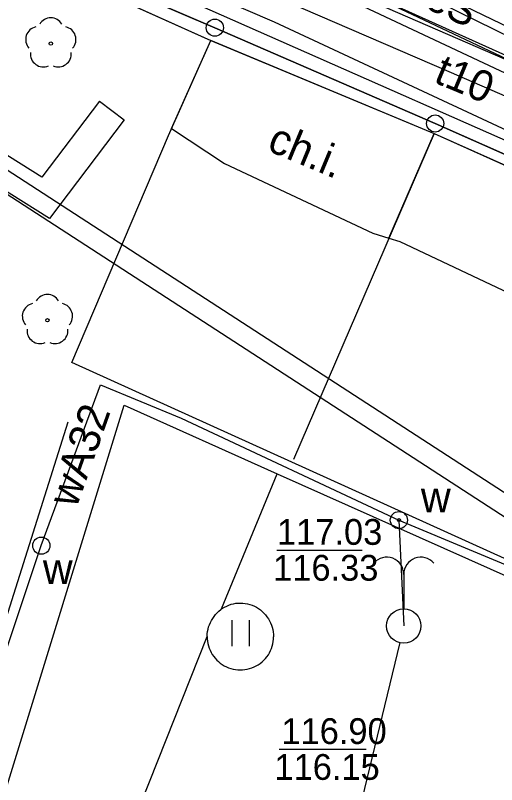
# Model space of a CAD drawing. Extents: x 6434771 to 6436222, y 5663454 to 5664782.
# Drawn here: x 6434897.1 to 6434911.12, y 5664046.13 to 5664068.5 of the extents above; entities that cross this region are included whole.
import ezdxf

# ---------------------------------------------------------------- set-up
doc = ezdxf.new("R2010")
doc.units = 0
for name, color, linetype in [('Warstwa 1', 7, 'Continuous'), ('Warstwa 10', 7, 'Continuous'), ('Warstwa 11', 7, 'Continuous'), ('Warstwa 12', 7, 'Continuous'), ('Warstwa 13', 7, 'Continuous'), ('Warstwa 14', 7, 'Continuous'), ('Warstwa 2', 7, 'Continuous'), ('Warstwa 32', 7, 'Continuous'), ('Warstwa 4', 7, 'Continuous'), ('Warstwa 5', 7, 'Continuous'), ('Warstwa 51', 7, 'Continuous'), ('Warstwa 6', 7, 'Continuous'), ('Warstwa 7', 7, 'Continuous'), ('Warstwa 8', 7, 'Continuous'), ('Warstwa 9', 7, 'Continuous')]:
    doc.layers.add(name, color=color, linetype=linetype)

msp = doc.modelspace()

# ---------------------------------------------------------------- linework, layer by layer
at = {"layer": 'Warstwa 1'}
for p, q in [((6434896.533, 5664070.874), (6434902.911, 5664068.147)), ((6434896.533, 5664070.874), (6434902.911, 5664068.147)), ((6434902.911, 5664068.147), (6434909.328, 5664065.359)), ((6434902.911, 5664068.147), (6434909.328, 5664065.359)), ((6434909.328, 5664065.359), (6434918.181, 5664061.441)), ((6434909.328, 5664065.359), (6434918.181, 5664061.441))]:
    msp.add_line(p, q, dxfattribs=at)
at = {"layer": 'Warstwa 10'}
for points in [[(6435039.27, 5663995.38), (6435030.2, 5664000.49), (6435026.78, 5664002.49), (6435005.3, 5664015.02), (6435001.82, 5664020.36), (6434989.95, 5664026.95), (6434987.82, 5664026.16), (6434986.6, 5664026.34), (6434978.53, 5664030.75), (6434978.42, 5664032.99), (6434977.19, 5664033.85), (6434965.42, 5664040.09), (6434950.99, 5664047.76), (6434936.21, 5664055.56), (6434923.51, 5664061.95), (6434922, 5664062.6), (6434919.82, 5664061.67), (6434916.14, 5664063.34), (6434915.04, 5664064.99), (6434913.7, 5664066.79), (6434899.99, 5664073.52), (6434899.07, 5664073.93), (6434899.76, 5664075.88), (6434904.43, 5664090.76)], [(6434898.671, 5664074.419), (6434902.76, 5664072.365), (6434912.576, 5664067.627), (6434922.039, 5664062.843), (6434928.491, 5664059.745), (6434937.421, 5664055.317), (6434945.409, 5664050.998), (6434960.407, 5664042.783), (6434962.523, 5664038.882), (6434979.882, 5664029.167), (6434995.86, 5664020.139), (6435019.103, 5664006.754), (6435039.449, 5663995.035), (6435046.546, 5663989.977), (6435049.657, 5663987.84), (6435051.881, 5663986.317), (6435053.049, 5663985.633), (6435057.374, 5663981.038), (6435060.712, 5663977.517), (6435062.186, 5663975.788), (6435062.844, 5663975.005)], [(6434897.799, 5664073.869), (6434902.99, 5664071.376), (6434906.697, 5664069.461), (6434912.456, 5664066.861), (6434925.794, 5664060.729), (6434928.609, 5664060.01), (6434931.137, 5664057.624), (6434949.054, 5664048.986), (6434962.469, 5664041.023), (6434978.882, 5664032.044), (6434990.046, 5664026.529), (6434993.502, 5664024.497), (6435013.504, 5664012.944), (6435029.359, 5664004.111), (6435038.639, 5663997.479)], [(6434896.42, 5664071.06), (6434898.16, 5664073.03), (6434900.23, 5664072.06), (6434923.31, 5664061.23), (6434926.55, 5664059.81), (6434927.25, 5664060), (6434930.24, 5664058.57), (6434930.73, 5664057.88), (6434948.57, 5664048.49), (6434986.66, 5664027.63), (6435008.6, 5664015.27), (6435029.24, 5664003.72), (6435037.15, 5663998.25), (6435049.94, 5663990.19), (6435056.65, 5663985.18), (6435065.79, 5663976.31), (6435067.86, 5663972.11), (6435071.01, 5663962.36), (6435072.82, 5663959.6), (6435082.35, 5663954.64), (6435097.639, 5663946.244)]]:
    msp.add_lwpolyline(points, dxfattribs=at)
for centre in [(6434902.911, 5664068.147), (6434902.911, 5664068.147), (6434909.328, 5664065.359), (6434909.328, 5664065.359)]:
    msp.add_circle(centre, 0.25, dxfattribs=at)
at = {"layer": 'Warstwa 11'}
for centre in [(6434898.135, 5664067.685), (6434898.037, 5664059.636)]:
    msp.add_circle(centre, 0.05, dxfattribs=at)
for centre, start, end in [((6434898.135, 5664068.06), 30.1471, 149.8529), ((6434897.778, 5664067.801), 102.1471, 221.8529), ((6434898.492, 5664067.801), 318.1471, 77.8529), ((6434897.915, 5664067.382), 174.1471, 293.8529), ((6434898.355, 5664067.382), 246.1471, 5.8529), ((6434898.037, 5664060.011), 30.1471, 149.8529), ((6434897.68, 5664059.752), 102.1471, 221.8529), ((6434898.394, 5664059.752), 318.1471, 77.8529), ((6434897.817, 5664059.333), 174.1471, 293.8529), ((6434898.257, 5664059.333), 246.1471, 5.8529)]:
    msp.add_arc(centre, 0.375, start, end, dxfattribs=at)
at = {"layer": 'Warstwa 12'}
for points in [[(6434879.175, 5664080.266), (6434887.31, 5664077.322), (6434892.172, 5664075.523), (6434893.714, 5664075.077), (6434894.712, 5664074.689), (6434895.613, 5664074.144), (6434901.244, 5664071.622), (6434919.521, 5664063.703), (6434922.709, 5664066.16)], [(6434879.17, 5664079.837), (6434888.273, 5664076.673), (6434888.682, 5664076.42), (6434889.766, 5664075.059), (6434890.197, 5664074.339), (6434897.825, 5664070.973), (6434901.691, 5664069.15), (6434915.855, 5664062.899), (6434925.788, 5664058.47), (6434925.899, 5664058.551), (6434931.693, 5664069.373), (6434935.652, 5664076.954)], [(6434879.158, 5664078.856), (6434884.466, 5664077.041), (6434884.943, 5664076.892), (6434885.361, 5664076.61), (6434904.643, 5664068.316), (6434925.269, 5664058.705), (6434945.05, 5664048.685), (6434974.567, 5664032.476), (6434974.989, 5664032.261), (6434975.127, 5664032.48), (6434976.891, 5664035.328), (6434977.019, 5664035.547), (6434977.471, 5664035.311), (6435021.423, 5664010.318), (6435021.865, 5664010.097), (6435021.856, 5664009.772), (6435020.661, 5664007.687), (6435020.508, 5664007.434), (6435020.935, 5664007.143), (6435043.134, 5663993.734), (6435056.442, 5663986.832), (6435065.286, 5663979.645), (6435065.567, 5663979.291)], [(6435076.981, 5663977.987), (6435060.8, 5663986.83), (6435044.672, 5663995.689), (6435035.779, 5664000.664), (6435026.559, 5664005.848), (6435021.216, 5664008.862), (6435015.543, 5664011.986), (6435005.727, 5664017.515), (6434993.895, 5664024.292), (6434988.15, 5664027.391), (6434986.652, 5664028.144), (6434985.953, 5664028.56), (6434978.495, 5664032.512), (6434971.253, 5664036.441), (6434966.665, 5664038.927), (6434949.941, 5664048.002), (6434948.145, 5664048.942), (6434947.222, 5664049.507), (6434943.986, 5664051.256), (6434934.8, 5664055.982), (6434925.516, 5664060.59), (6434905.925, 5664069.826), (6434896.606, 5664074.336), (6434894.752, 5664075.227)], [(6434922.621, 5664060.807), (6434921.342, 5664061.827), (6434909.738, 5664066.86), (6434900.244, 5664070.967), (6434893.585, 5664073.988), (6434892.737, 5664074.562)], [(6434885.395, 5664013.843), (6434885.756, 5664014.964), (6434886.868, 5664018.391), (6434887.895, 5664021.449), (6434889.709, 5664026.787), (6434891.413, 5664032.026), (6434892.752, 5664036.89), (6434894.005, 5664041.255), (6434895.856, 5664047.122), (6434897.858, 5664053.078), (6434899.585, 5664057.757), (6434901.933, 5664056.788), (6434908.273, 5664053.821), (6434914.766, 5664051.112), (6434915.042, 5664051.579), (6434915.735, 5664051.851), (6434916.557, 5664052.021), (6434918.057, 5664051.142), (6434918.098, 5664051.124), (6434921.598, 5664049.539), (6434922.532, 5664051.558), (6434923.03, 5664051.342), (6434925.581, 5664050.171)], [(6434908.273, 5664053.821), (6434908.415, 5664050.742)]]:
    msp.add_lwpolyline(points, dxfattribs=at)
at = {"layer": 'Warstwa 14'}
for p, q in [((6434907.207, 5664052.94), (6434904.715, 5664052.94)), ((6434907.321, 5664047.147), (6434904.786, 5664047.147))]:
    msp.add_line(p, q, dxfattribs=at)
msp.add_circle((6434908.273, 5664053.821), 0.045, dxfattribs=at)
at = {"layer": 'Warstwa 2'}
for points in [[(6434878.725, 5664042.975), (6434879.824, 5664045.447), (6434885.357, 5664054.75), (6434896.533, 5664070.874), (6434897.518, 5664070.15), (6434902.796, 5664067.777)], [(6434901.563, 5664065.013), (6434902.796, 5664067.777)], [(6434902.788, 5664067.781), (6434909.299, 5664065.072)], [(6434938.699, 5664047.811), (6434932.805, 5664050.893), (6434931.278, 5664047.842), (6434922.18, 5664052.192), (6434921.428, 5664050.352), (6434915.161, 5664053.198), (6434914.349, 5664051.348), (6434898.743, 5664058.407), (6434901.563, 5664065.013)], [(6434909.299, 5664065.072), (6434905.207, 5664055.585)], [(6434909.299, 5664065.072), (6434918.25, 5664061.052)], [(6434885.156, 5664013.984), (6434898.642, 5664056.678)]]:
    msp.add_lwpolyline(points, dxfattribs=at)
at = {"layer": 'Warstwa 32'}
msp.add_line((6434908.415, 5664052.242), (6434908.415, 5664051.242), dxfattribs=at)
msp.add_circle((6434908.415, 5664050.742), 0.5, dxfattribs=at)
for centre, start, end in [((6434907.915, 5664052.242), 0, 138.5904), ((6434908.915, 5664052.242), 41.4096, 180)]:
    msp.add_arc(centre, 0.5, start, end, dxfattribs=at)
at = {"layer": 'Warstwa 4'}
for centre in [(6434908.273, 5664053.821), (6434897.858, 5664053.078)]:
    msp.add_circle(centre, 0.25, dxfattribs=at)
at = {"layer": 'Warstwa 5'}
for p, q in [((6434903.138, 5664051.256), (6434903.198, 5664051.291)), ((6434903.198, 5664051.291), (6434903.259, 5664051.322)), ((6434903.259, 5664051.322), (6434903.323, 5664051.349)), ((6434903.323, 5664051.349), (6434903.389, 5664051.371)), ((6434903.389, 5664051.371), (6434903.456, 5664051.388)), ((6434903.456, 5664051.388), (6434903.524, 5664051.4)), ((6434903.524, 5664051.4), (6434903.593, 5664051.407)), ((6434903.593, 5664051.407), (6434903.662, 5664051.409)), ((6434903.662, 5664051.409), (6434903.731, 5664051.406)), ((6434903.731, 5664051.406), (6434903.799, 5664051.398)), ((6434903.799, 5664051.398), (6434903.867, 5664051.385)), ((6434903.867, 5664051.385), (6434903.934, 5664051.367)), ((6434903.934, 5664051.367), (6434903.999, 5664051.345)), ((6434903.999, 5664051.345), (6434904.063, 5664051.317)), ((6434904.063, 5664051.317), (6434904.124, 5664051.286)), ((6434904.124, 5664051.286), (6434904.183, 5664051.249)), ((6434902.889, 5664051.02), (6434902.932, 5664051.074)), ((6434902.932, 5664051.074), (6434902.978, 5664051.125)), ((6434902.978, 5664051.125), (6434903.028, 5664051.172)), ((6434903.028, 5664051.172), (6434903.082, 5664051.216)), ((6434903.082, 5664051.216), (6434903.11, 5664051.236)), ((6434903.11, 5664051.236), (6434903.138, 5664051.256)), ((6434904.183, 5664051.249), (6434904.239, 5664051.209)), ((6434904.239, 5664051.209), (6434904.292, 5664051.165)), ((6434904.292, 5664051.165), (6434904.342, 5664051.117)), ((6434904.342, 5664051.117), (6434904.388, 5664051.065)), ((6434904.388, 5664051.065), (6434904.43, 5664051.01)), ((6434902.755, 5664050.778), (6434902.782, 5664050.842)), ((6434902.782, 5664050.842), (6434902.814, 5664050.903)), ((6434902.814, 5664050.903), (6434902.85, 5664050.962)), ((6434902.85, 5664050.962), (6434902.889, 5664051.02)), ((6434903.421, 5664050.156), (6434903.421, 5664050.906)), ((6434903.921, 5664050.156), (6434903.921, 5664050.906)), ((6434904.43, 5664051.01), (6434904.47, 5664050.953)), ((6434904.47, 5664050.953), (6434904.505, 5664050.894)), ((6434904.505, 5664050.894), (6434904.536, 5664050.832)), ((6434904.536, 5664050.832), (6434904.563, 5664050.768)), ((6434902.701, 5664050.577), (6434902.714, 5664050.645)), ((6434902.714, 5664050.645), (6434902.732, 5664050.712)), ((6434902.732, 5664050.712), (6434902.755, 5664050.778)), ((6434904.563, 5664050.768), (6434904.585, 5664050.702)), ((6434904.585, 5664050.702), (6434904.602, 5664050.635)), ((6434904.602, 5664050.635), (6434904.614, 5664050.567)), ((6434902.69, 5664050.439), (6434902.693, 5664050.509)), ((6434902.69, 5664050.439), (6434902.692, 5664050.37)), ((6434902.693, 5664050.509), (6434902.701, 5664050.577)), ((6434904.614, 5664050.567), (6434904.622, 5664050.498)), ((6434904.622, 5664050.498), (6434904.624, 5664050.429)), ((6434904.622, 5664050.36), (6434904.624, 5664050.429)), ((6434902.692, 5664050.37), (6434902.698, 5664050.301)), ((6434902.698, 5664050.301), (6434902.71, 5664050.233)), ((6434902.71, 5664050.233), (6434902.726, 5664050.166)), ((6434902.726, 5664050.166), (6434902.748, 5664050.1)), ((6434904.563, 5664050.09), (6434904.585, 5664050.156)), ((6434904.585, 5664050.156), (6434904.602, 5664050.223)), ((6434904.602, 5664050.223), (6434904.614, 5664050.291)), ((6434904.614, 5664050.291), (6434904.622, 5664050.36)), ((6434902.748, 5664050.1), (6434902.773, 5664050.035)), ((6434902.773, 5664050.035), (6434902.804, 5664049.973)), ((6434902.804, 5664049.973), (6434902.839, 5664049.913)), ((6434904.47, 5664049.904), (6434904.505, 5664049.964)), ((6434904.505, 5664049.964), (6434904.536, 5664050.026)), ((6434904.536, 5664050.026), (6434904.563, 5664050.09)), ((6434902.839, 5664049.913), (6434902.878, 5664049.856)), ((6434902.878, 5664049.856), (6434902.921, 5664049.802)), ((6434902.921, 5664049.802), (6434902.968, 5664049.751)), ((6434902.968, 5664049.751), (6434903.018, 5664049.703)), ((6434903.018, 5664049.703), (6434903.071, 5664049.659)), ((6434904.288, 5664049.696), (6434904.339, 5664049.743)), ((6434904.339, 5664049.743), (6434904.386, 5664049.794)), ((6434904.386, 5664049.794), (6434904.43, 5664049.848)), ((6434904.43, 5664049.848), (6434904.47, 5664049.904)), ((6434903.071, 5664049.659), (6434903.128, 5664049.619)), ((6434903.128, 5664049.619), (6434903.187, 5664049.583)), ((6434903.187, 5664049.583), (6434903.249, 5664049.552)), ((6434903.249, 5664049.552), (6434903.313, 5664049.525)), ((6434903.313, 5664049.525), (6434903.379, 5664049.503)), ((6434903.379, 5664049.503), (6434903.446, 5664049.485)), ((6434903.446, 5664049.485), (6434903.514, 5664049.472)), ((6434903.79, 5664049.471), (6434903.858, 5664049.483)), ((6434903.858, 5664049.483), (6434903.925, 5664049.5)), ((6434903.925, 5664049.5), (6434903.991, 5664049.521)), ((6434903.991, 5664049.521), (6434904.055, 5664049.548)), ((6434904.055, 5664049.548), (6434904.117, 5664049.578)), ((6434904.117, 5664049.578), (6434904.177, 5664049.614)), ((6434904.177, 5664049.614), (6434904.234, 5664049.653)), ((6434904.234, 5664049.653), (6434904.288, 5664049.696)), ((6434903.514, 5664049.472), (6434903.583, 5664049.465)), ((6434903.583, 5664049.465), (6434903.652, 5664049.462)), ((6434903.652, 5664049.462), (6434903.721, 5664049.464)), ((6434903.721, 5664049.464), (6434903.79, 5664049.471))]:
    msp.add_line(p, q, dxfattribs=at)
at = {"layer": 'Warstwa 51'}
for points in [[(6434899.551, 5664066.011), (6434900.268, 5664065.469), (6434898.093, 5664062.595), (6434894.56, 5664064.808), (6434895.037, 5664065.57)], [(6434899.551, 5664066.011), (6434897.873, 5664063.795), (6434895.037, 5664065.57)]]:
    msp.add_lwpolyline(points, dxfattribs=at)
at = {"layer": 'Warstwa 6'}
msp.add_lwpolyline([(6434910.046, 5664089.201), (6434907.804, 5664089.868), (6434906.064, 5664090.689), (6434905.401, 5664091.287), (6434905.176, 5664091.7), (6434905.052, 5664092.201), (6434898.465, 5664094.951), (6434890.58, 5664073.12), (6434890.292, 5664072.48), (6434896.533, 5664070.874), (6434902.911, 5664068.147), (6434909.328, 5664065.359), (6434918.181, 5664061.441), (6434925.132, 5664058.117), (6434933.864, 5664054.041), (6434942.859, 5664049.431), (6434957.736, 5664068.872)], close=True, dxfattribs=at)
msp.add_lwpolyline([(6435199.169, 5663878.85), (6435069.683, 5663952.11), (6435070.435, 5663958.091), (6435069.483, 5663961.233), (6435068.325, 5663963.837), (6435062.043, 5663974.514), (6435058.095, 5663979.622), (6435055.831, 5663981.839), (6435050.759, 5663985.791), (6435026.957, 5664002.35), (6434999.334, 5664017.996), (6434991.09, 5664022.666), (6434980.58, 5664028.593), (6434951.952, 5664044.671), (6434942.859, 5664049.431), (6434933.864, 5664054.041), (6434925.132, 5664058.117), (6434918.181, 5664061.441), (6434909.328, 5664065.359), (6434902.911, 5664068.147), (6434896.533, 5664070.874)], dxfattribs=at)
msp.add_circle((6434908.273, 5664053.821), 0.045, dxfattribs=at)
at = {"layer": 'Warstwa 7'}
msp.add_lwpolyline([(6434931.805, 5664040.206), (6434931.787, 5664040.222), (6434928.208, 5664042.939), (6434927.618, 5664043.361), (6434881.848, 5664073.028), (6434882.174, 5664073.532), (6434927.956, 5664043.857), (6434928.564, 5664043.423), (6434932.177, 5664040.68), (6434932.182, 5664040.675), (6434932.526, 5664039.935)], close=True, dxfattribs=at)
msp.add_lwpolyline([(6434908.297, 5664050.256), (6434907.194, 5664045.691), (6434926.866, 5664041.905), (6434927.988, 5664038.822)], dxfattribs=at)
at = {"layer": 'Warstwa 8'}
for p, q in [((6434897.518, 5664070.15), (6434902.796, 5664067.778)), ((6434902.796, 5664067.778), (6434909.299, 5664065.072)), ((6434909.299, 5664065.072), (6434918.25, 5664061.052))]:
    msp.add_line(p, q, dxfattribs=at)
at = {"layer": 'Warstwa 9'}
for p, q in [((6434901.652, 5664065.212), (6434902.796, 5664067.778)), ((6434902.796, 5664067.778), (6434909.299, 5664065.072)), ((6434901.652, 5664065.212), (6434903.194, 5664064.2)), ((6434907.984, 5664062.024), (6434909.299, 5664065.072)), ((6434907.984, 5664062.024), (6434909.299, 5664065.072)), ((6434909.299, 5664065.072), (6434918.25, 5664061.052)), ((6434903.194, 5664064.2), (6434907.517, 5664062.164)), ((6434907.517, 5664062.164), (6434907.984, 5664062.024)), ((6434907.984, 5664062.024), (6434908.303, 5664061.928)), ((6434908.303, 5664061.928), (6434913.242, 5664059.593)), ((6434895.35, 5664041.176), (6434900.271, 5664057.163)), ((6434900.271, 5664057.163), (6434904.731, 5664055.169)), ((6434903.11, 5664051.236), (6434904.731, 5664055.169)), ((6434903.11, 5664051.236), (6434904.731, 5664055.169)), ((6434904.731, 5664055.169), (6434914.546, 5664050.782)), ((6434903.138, 5664051.256), (6434903.198, 5664051.291)), ((6434903.198, 5664051.291), (6434903.259, 5664051.322)), ((6434903.259, 5664051.322), (6434903.323, 5664051.349)), ((6434903.323, 5664051.349), (6434903.389, 5664051.371)), ((6434903.389, 5664051.371), (6434903.456, 5664051.388)), ((6434903.456, 5664051.388), (6434903.524, 5664051.4)), ((6434903.524, 5664051.4), (6434903.593, 5664051.407)), ((6434903.593, 5664051.407), (6434903.662, 5664051.409)), ((6434903.662, 5664051.409), (6434903.731, 5664051.406)), ((6434903.731, 5664051.406), (6434903.799, 5664051.398)), ((6434903.799, 5664051.398), (6434903.867, 5664051.385)), ((6434903.867, 5664051.385), (6434903.934, 5664051.367)), ((6434903.934, 5664051.367), (6434903.999, 5664051.345)), ((6434903.999, 5664051.345), (6434904.063, 5664051.317)), ((6434904.063, 5664051.317), (6434904.124, 5664051.286)), ((6434904.124, 5664051.286), (6434904.183, 5664051.249)), ((6434902.889, 5664051.02), (6434902.932, 5664051.074)), ((6434902.932, 5664051.074), (6434902.978, 5664051.125)), ((6434902.978, 5664051.125), (6434903.028, 5664051.172)), ((6434903.028, 5664051.172), (6434903.082, 5664051.216)), ((6434903.082, 5664051.216), (6434903.11, 5664051.236)), ((6434903.11, 5664051.236), (6434903.138, 5664051.256)), ((6434904.183, 5664051.249), (6434904.239, 5664051.209)), ((6434904.239, 5664051.209), (6434904.292, 5664051.165)), ((6434904.292, 5664051.165), (6434904.342, 5664051.117)), ((6434904.342, 5664051.117), (6434904.388, 5664051.065)), ((6434904.388, 5664051.065), (6434904.43, 5664051.01)), ((6434902.755, 5664050.778), (6434902.782, 5664050.842)), ((6434902.782, 5664050.842), (6434902.814, 5664050.903)), ((6434902.814, 5664050.903), (6434902.85, 5664050.962)), ((6434902.85, 5664050.962), (6434902.889, 5664051.02)), ((6434904.43, 5664051.01), (6434904.47, 5664050.953)), ((6434904.47, 5664050.953), (6434904.505, 5664050.894)), ((6434904.505, 5664050.894), (6434904.536, 5664050.832)), ((6434904.536, 5664050.832), (6434904.563, 5664050.768)), ((6434902.701, 5664050.577), (6434902.714, 5664050.645)), ((6434902.714, 5664050.645), (6434902.732, 5664050.712)), ((6434902.732, 5664050.712), (6434902.755, 5664050.778)), ((6434904.563, 5664050.768), (6434904.585, 5664050.702)), ((6434904.585, 5664050.702), (6434904.602, 5664050.635)), ((6434904.602, 5664050.635), (6434904.614, 5664050.567)), ((6434899.079, 5664041.374), (6434902.69, 5664050.439)), ((6434899.079, 5664041.374), (6434902.69, 5664050.439)), ((6434902.69, 5664050.439), (6434902.693, 5664050.509)), ((6434902.69, 5664050.439), (6434902.692, 5664050.37)), ((6434902.693, 5664050.509), (6434902.701, 5664050.577)), ((6434904.614, 5664050.567), (6434904.622, 5664050.498)), ((6434904.622, 5664050.498), (6434904.624, 5664050.429)), ((6434904.622, 5664050.36), (6434904.624, 5664050.429)), ((6434902.692, 5664050.37), (6434902.698, 5664050.301)), ((6434902.698, 5664050.301), (6434902.71, 5664050.233)), ((6434902.71, 5664050.233), (6434902.726, 5664050.166)), ((6434902.726, 5664050.166), (6434902.748, 5664050.1)), ((6434904.563, 5664050.09), (6434904.585, 5664050.156)), ((6434904.585, 5664050.156), (6434904.602, 5664050.223)), ((6434904.602, 5664050.223), (6434904.614, 5664050.291)), ((6434904.614, 5664050.291), (6434904.622, 5664050.36)), ((6434902.748, 5664050.1), (6434902.773, 5664050.035)), ((6434902.773, 5664050.035), (6434902.804, 5664049.973)), ((6434902.804, 5664049.973), (6434902.839, 5664049.913)), ((6434904.47, 5664049.904), (6434904.505, 5664049.964)), ((6434904.505, 5664049.964), (6434904.536, 5664050.026)), ((6434904.536, 5664050.026), (6434904.563, 5664050.09)), ((6434902.839, 5664049.913), (6434902.878, 5664049.856)), ((6434902.878, 5664049.856), (6434902.921, 5664049.802)), ((6434902.921, 5664049.802), (6434902.968, 5664049.751)), ((6434902.968, 5664049.751), (6434903.018, 5664049.703)), ((6434903.018, 5664049.703), (6434903.071, 5664049.659)), ((6434904.288, 5664049.696), (6434904.339, 5664049.743)), ((6434904.339, 5664049.743), (6434904.386, 5664049.794)), ((6434904.386, 5664049.794), (6434904.43, 5664049.848)), ((6434904.43, 5664049.848), (6434904.47, 5664049.904)), ((6434903.071, 5664049.659), (6434903.128, 5664049.619)), ((6434903.128, 5664049.619), (6434903.187, 5664049.583)), ((6434903.187, 5664049.583), (6434903.249, 5664049.552)), ((6434903.249, 5664049.552), (6434903.313, 5664049.525)), ((6434903.313, 5664049.525), (6434903.379, 5664049.503)), ((6434903.379, 5664049.503), (6434903.446, 5664049.485)), ((6434903.446, 5664049.485), (6434903.514, 5664049.472)), ((6434903.79, 5664049.471), (6434903.858, 5664049.483)), ((6434903.858, 5664049.483), (6434903.925, 5664049.5)), ((6434903.925, 5664049.5), (6434903.991, 5664049.521)), ((6434903.991, 5664049.521), (6434904.055, 5664049.548)), ((6434904.055, 5664049.548), (6434904.117, 5664049.578)), ((6434904.117, 5664049.578), (6434904.177, 5664049.614)), ((6434904.177, 5664049.614), (6434904.234, 5664049.653)), ((6434904.234, 5664049.653), (6434904.288, 5664049.696)), ((6434903.514, 5664049.472), (6434903.583, 5664049.465)), ((6434903.583, 5664049.465), (6434903.652, 5664049.462)), ((6434903.652, 5664049.462), (6434903.721, 5664049.464)), ((6434903.721, 5664049.464), (6434903.79, 5664049.471))]:
    msp.add_line(p, q, dxfattribs=at)

# ---------------------------------------------------------------- texts
at = {"layer": 'Warstwa 11'}
msp.add_text('6eS', height=0.9, rotation=334.9282, dxfattribs=at).set_placement((6434908.365, 5664069.038))
msp.add_text('6eS', height=0.9, rotation=334.9282, dxfattribs=at).set_placement((6434908.365, 5664069.038))
at = {"layer": 'Warstwa 13'}
for s, rotation, p in [('t10', 337.2487, (6434909.252, 5664066.571)), ('wA32', 70.4394, (6434898.878, 5664054.148))]:
    msp.add_text(s, height=0.9, rotation=rotation, dxfattribs=at).set_placement(p)
at = {"layer": 'Warstwa 14'}
for s, p in [('116.33', (6434904.609, 5664052.059)), ('116.15', (6434904.647, 5664046.265))]:
    msp.add_text(s, height=0.75, dxfattribs=at).set_placement(p)
at = {"layer": 'Warstwa 5'}
for p in [(6434908.913, 5664054.045), (6434897.903, 5664051.964)]:
    msp.add_text('w', height=0.9, dxfattribs=at).set_placement(p)
at = {"layer": 'Warstwa 6'}
for s, p in [('117.03', (6434904.723, 5664053.102)), ('116.90', (6434904.85, 5664047.308))]:
    msp.add_text(s, height=0.75, dxfattribs=at).set_placement(p)
at = {"layer": 'Warstwa 9'}
msp.add_text('ch.i.', height=0.9, rotation=337.4091, dxfattribs=at).set_placement((6434904.397, 5664064.587))

doc.saveas('drawing.dxf')
